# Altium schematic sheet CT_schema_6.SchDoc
size 372 x 245 mm
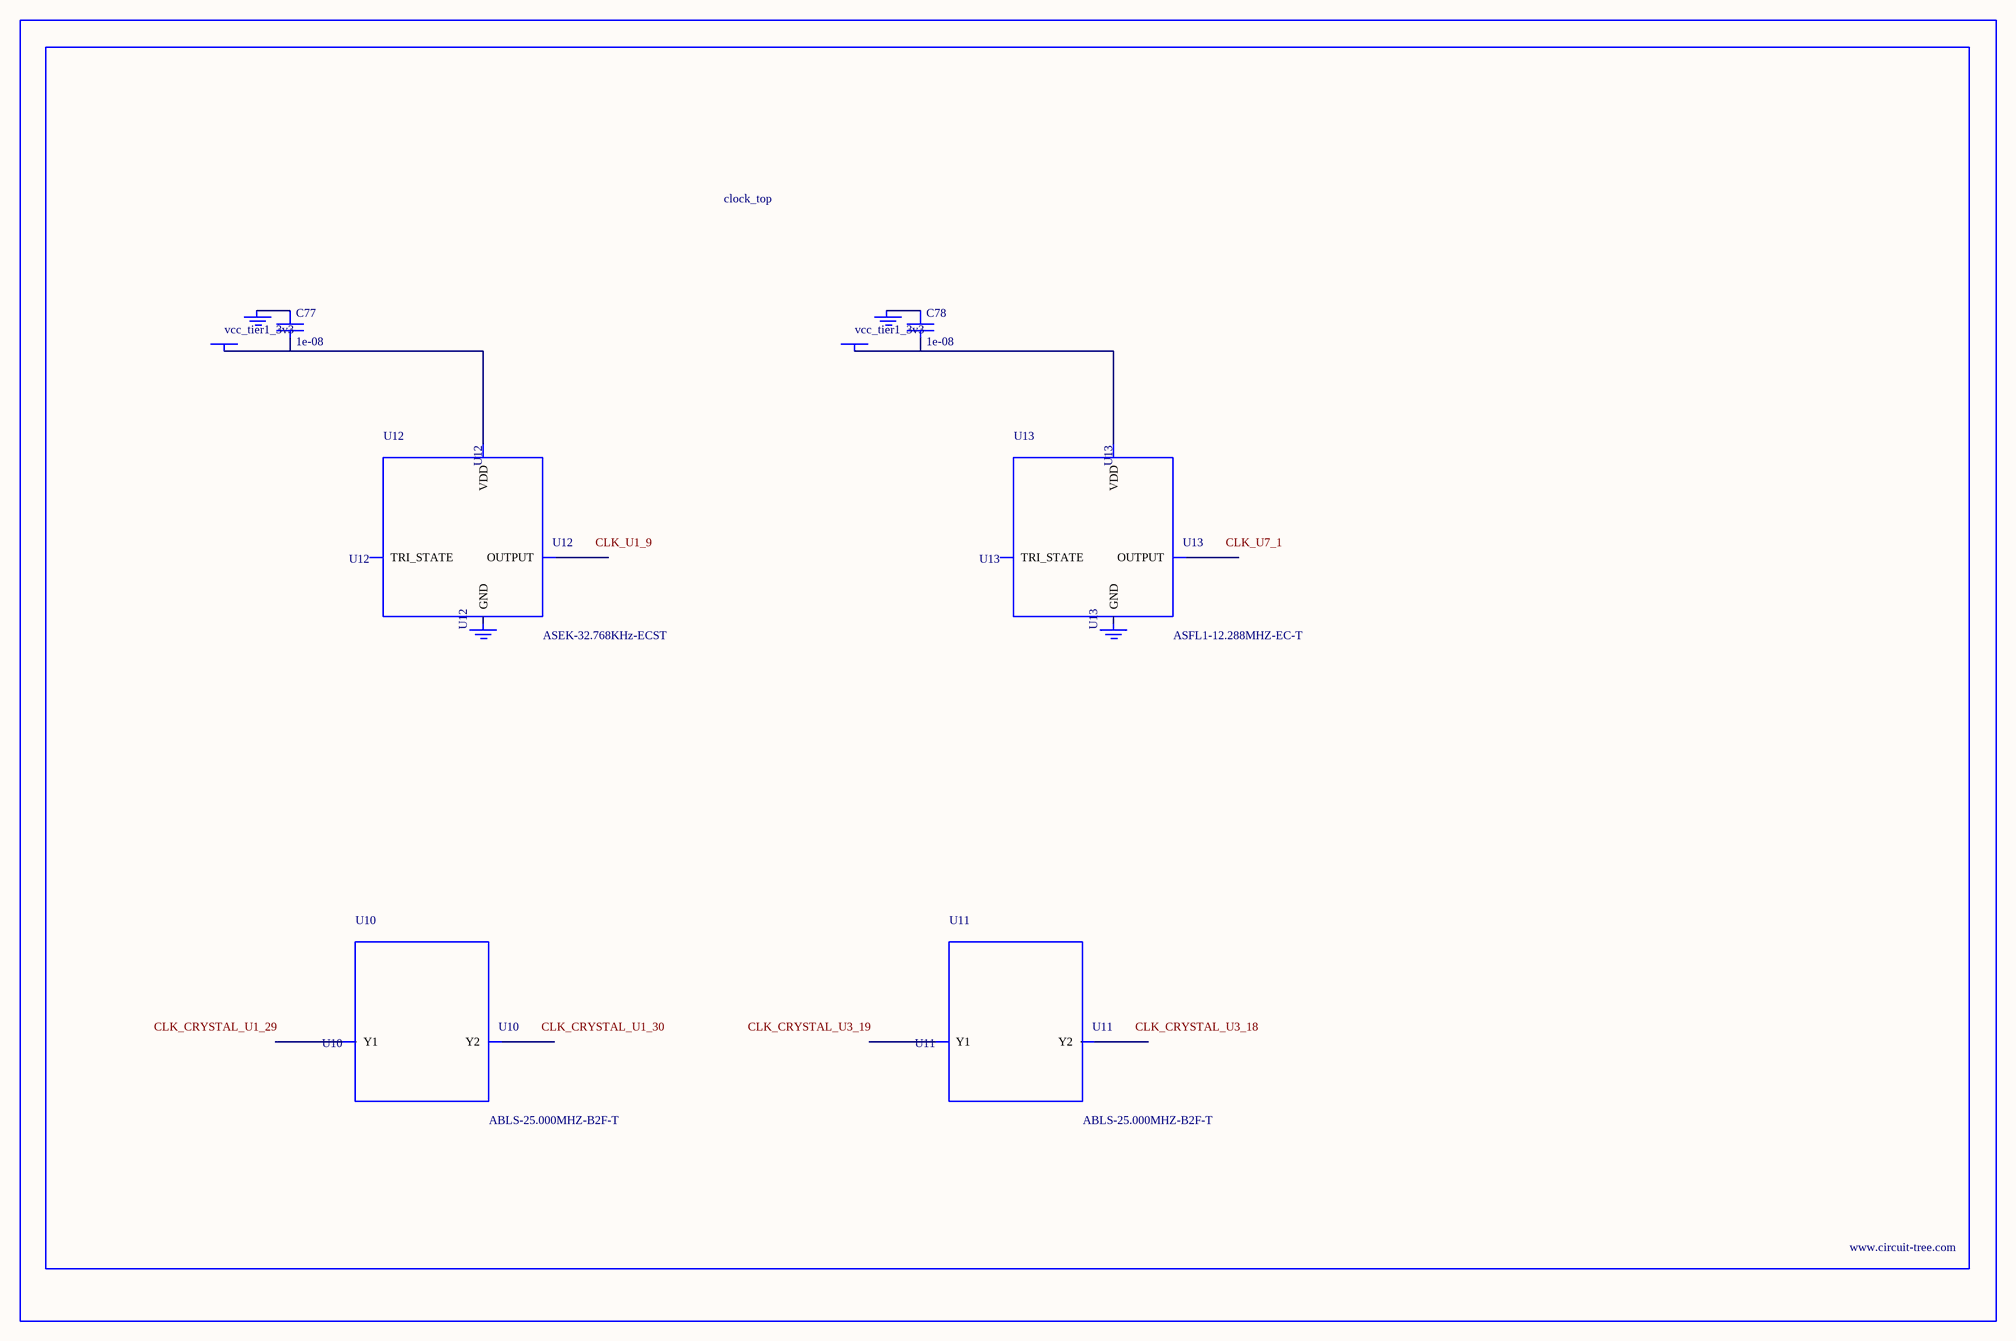
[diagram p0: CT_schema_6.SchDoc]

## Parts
BORDER5  (no value)
C77  1e-08  [C0402]
C78  1e-08  [C0402]
GND_INSTANCE_5_0  (no value)
GND_INSTANCE_5_1  (no value)
GND_INSTANCE_5_2  (no value)
GND_INSTANCE_5_3  (no value)
POWER_INSTANCE_5_0  vcc_tier1_3v3
POWER_INSTANCE_5_1  vcc_tier1_3v3
U10  ABLS-25.000MHZ-B2F-T  [ABLS-25.000MHZ-B2F-T]
U11  ABLS-25.000MHZ-B2F-T  [ABLS-25.000MHZ-B2F-T]
U12  ASEK-32.768KHz-ECST  [ASEK]
U13  ASFL1-12.288MHZ-EC-T  [ASFL1]

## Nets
NetC77_1: C77.1 GND_INSTANCE_5_0.0(GND)
NetC77_2: C77.2 POWER_INSTANCE_5_0.0(PWR) U12.4(VDD)
NetC78_1: C78.1 GND_INSTANCE_5_2.0(GND)
NetC78_2: C78.2 POWER_INSTANCE_5_1.0(PWR) U13.4(VDD)

Not connected (* = marked no-connect by the designer): GND_INSTANCE_5_1 0(GND); GND_INSTANCE_5_3 0(GND); U10 1(Y1) 2(Y2); U11 1(Y1) 2(Y2); U12 1(TRI_STATE) 2(GND) 3(OUTPUT); U13 1(TRI_STATE) 2(GND) 3(OUTPUT)

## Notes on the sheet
- Labels drawn without touching a wire or pin: CLK_CRYSTAL_U1_29, CLK_CRYSTAL_U1_30, CLK_CRYSTAL_U3_18, CLK_CRYSTAL_U3_19, CLK_U1_9, CLK_U7_1

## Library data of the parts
BORDER5 = BORDER_PAGE5
C77 C78 = C0402C103K3RAC
GND_INSTANCE_5_0-GND_INSTANCE_5_3 = GND
POWER_INSTANCE_5_0 POWER_INSTANCE_5_1 = PWR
